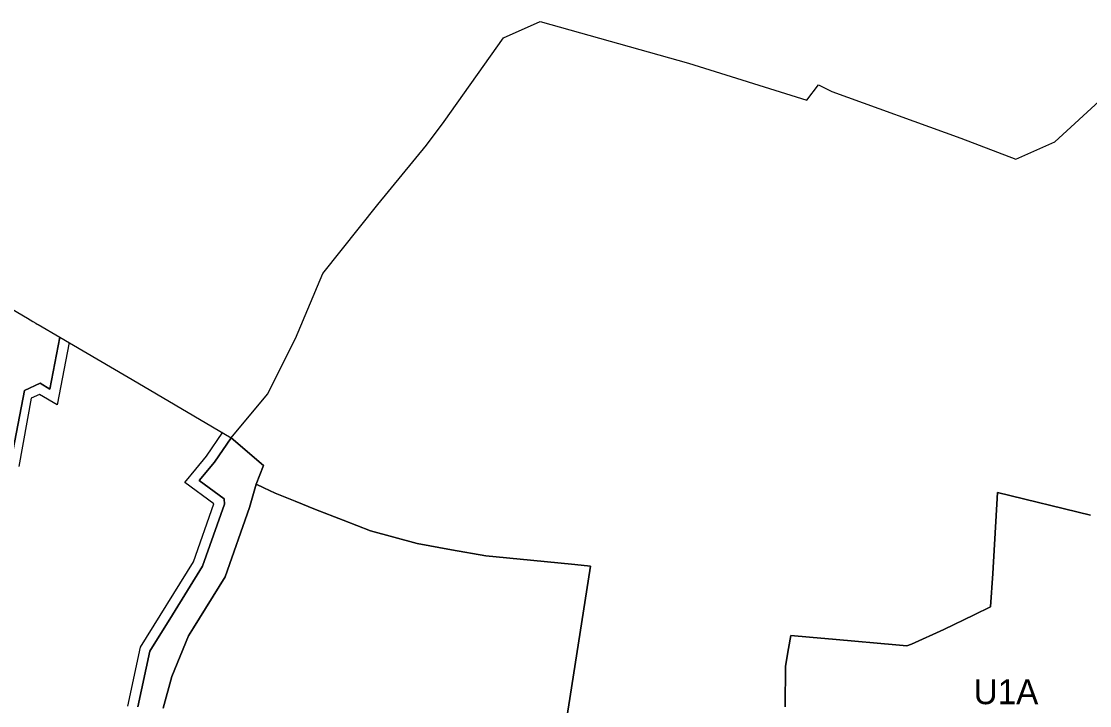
# Model space of a CAD drawing. Extents: x 7439486 to 7443435, y 5551288 to 5554556.
# Drawn here: x 7441655.2 to 7442085.2, y 5553616.6 to 5553892 of the extents above; entities that cross this region are included whole.
import ezdxf

# ---------------------------------------------------------------- set-up
doc = ezdxf.new("R2010")
doc.units = 0
for name, color, linetype in [('linie_rozgraniczajace', 7, 'Continuous'), ('linie_zabudowy_nieprzekraczalne', 7, 'Continuous'), ('oznaczenia_przeznaczen', 7, 'Continuous')]:
    doc.layers.add(name, color=color, linetype=linetype)

msp = doc.modelspace()

# ---------------------------------------------------------------- linework, layer by layer
at = {"layer": 'linie_rozgraniczajace'}
for points in [[(7441739.62, 5553724.39), (7441754.25, 5553741.96), (7441765.59, 5553764.43), (7441776.52, 5553790.47), (7441798.73, 5553818.38), (7441818.23, 5553842.21), (7441825.39, 5553851.77), (7441849.31, 5553885.42), (7441864, 5553892.05), (7441923.7, 5553875.21), (7441971.38, 5553860.28), (7441976.06, 5553866.48), (7441981.4, 5553863.87), (7442033.46, 5553844.96), (7442055.48, 5553836.54), (7442071.28, 5553843.59), (7442090.65, 5553861.37)], [(7441621.66, 5553563.33), (7441656.43, 5553743.48), (7441662.75, 5553746.34), (7441666.72, 5553744.02), (7441670.74, 5553764.84), (7441702.09, 5553746.49), (7441739.62, 5553724.39), (7441732.89, 5553714.63), (7441726.8, 5553707.15), (7441736.79, 5553699.75), (7441736.95, 5553697.68), (7441728.17, 5553672.71), (7441715.99, 5553653.12), (7441706.94, 5553638.55), (7441702.12, 5553616.12)], [(7441702.12, 5553616.12), (7441706.94, 5553638.55), (7441715.99, 5553653.12), (7441728.17, 5553672.71), (7441736.95, 5553697.68), (7441736.79, 5553699.75), (7441726.8, 5553707.15), (7441732.89, 5553714.63), (7441739.62, 5553724.39), (7441752.66, 5553713.26), (7441749.76, 5553705.71), (7441747.09, 5553696.36), (7441737.24, 5553668.36), (7441724.48, 5553647.84), (7441722.51, 5553644.66), (7441715.77, 5553628.35), (7441712.24, 5553615.6)], [(7441870.31, 5553583.46), (7441877.29, 5553628.08), (7441884.26, 5553672.71), (7441878.04, 5553673.32), (7441860.11, 5553675.07), (7441842.18, 5553676.82), (7441828.33, 5553679.3), (7441814.47, 5553681.77), (7441805.13, 5553684.38), (7441795.8, 5553686.99), (7441784.71, 5553691.28), (7441773.62, 5553695.58), (7441765.47, 5553698.86), (7441757.32, 5553702.14), (7441752.86, 5553704.25), (7441749.76, 5553705.71), (7441752.66, 5553713.26), (7441739.62, 5553724.39)], [(7441712.24, 5553615.6), (7441715.77, 5553628.35), (7441722.51, 5553644.66), (7441724.48, 5553647.84), (7441737.24, 5553668.36), (7441747.09, 5553696.36), (7441749.76, 5553705.71), (7441752.86, 5553704.25), (7441757.32, 5553702.14), (7441765.47, 5553698.86), (7441773.62, 5553695.58), (7441784.71, 5553691.28), (7441795.8, 5553686.99), (7441805.13, 5553684.38), (7441814.47, 5553681.77), (7441828.33, 5553679.3), (7441842.18, 5553676.82), (7441860.11, 5553675.07), (7441878.04, 5553673.32), (7441884.26, 5553672.71), (7441877.29, 5553628.08), (7441870.31, 5553583.46)], [(7442085.63, 5553693.26), (7442048.15, 5553702.41), (7442046.3, 5553669.73), (7442045.37, 5553656.33), (7442038.83, 5553653.14), (7442026.56, 5553647.16), (7442013.56, 5553641.24), (7442011.62, 5553640.67), (7442007.18, 5553641.06), (7441983.15, 5553643.19), (7441972.49, 5553644.14), (7441964.93, 5553644.81), (7441964, 5553639.52), (7441962.75, 5553632.44), (7441962.74, 5553616.11)], [(7441962.74, 5553616.11), (7441962.75, 5553632.44), (7441964, 5553639.52), (7441964.93, 5553644.81), (7441972.49, 5553644.14), (7441983.15, 5553643.19), (7442007.18, 5553641.06), (7442011.62, 5553640.67), (7442013.56, 5553641.24), (7442026.56, 5553647.16), (7442038.83, 5553653.14), (7442045.37, 5553656.33), (7442046.3, 5553669.73), (7442048.15, 5553702.41), (7442085.63, 5553693.26)]]:
    msp.add_lwpolyline(points, dxfattribs=at)
msp.add_lwpolyline([(7441564.02, 5553388.84), (7441571.87, 5553390.96), (7441582.79, 5553412.21), (7441583.1, 5553413.85), (7441583.19, 5553414.34), (7441610.84, 5553560.54), (7441635.49, 5553687.72), (7441651.46, 5553776.19), (7441657.69, 5553772.51), (7441659.87, 5553771.21), (7441661.04, 5553770.52), (7441661.58, 5553770.2), (7441661.94, 5553769.99), (7441670.74, 5553764.84), (7441666.72, 5553744.02), (7441662.75, 5553746.34), (7441656.43, 5553743.48), (7441621.66, 5553563.33), (7441592.35, 5553408.93), (7441580.43, 5553385.74), (7441582.74, 5553377.39), (7441574.96, 5553382.15), (7441564.12, 5553388.78)], close=True, dxfattribs=at)
at = {"layer": 'linie_zabudowy_nieprzekraczalne'}
for points in [[(7441674.4, 5553762.7), (7441669.57, 5553737.71), (7441662.51, 5553741.85), (7441659.21, 5553740.35), (7441654.24, 5553712.79)], [(7441698.07, 5553616.33), (7441703.17, 5553640.07), (7441724.54, 5553674.45), (7441732.74, 5553697.77), (7441721.05, 5553706.43), (7441725.37, 5553711.73), (7441729.69, 5553717.03), (7441736.33, 5553726.66)]]:
    msp.add_lwpolyline(points, dxfattribs=at)

# ---------------------------------------------------------------- texts
at = {"layer": 'oznaczenia_przeznaczen'}
msp.add_text('U1A', height=10, dxfattribs=at).set_placement((7442038.57, 5553617.14))

doc.saveas('drawing.dxf')
